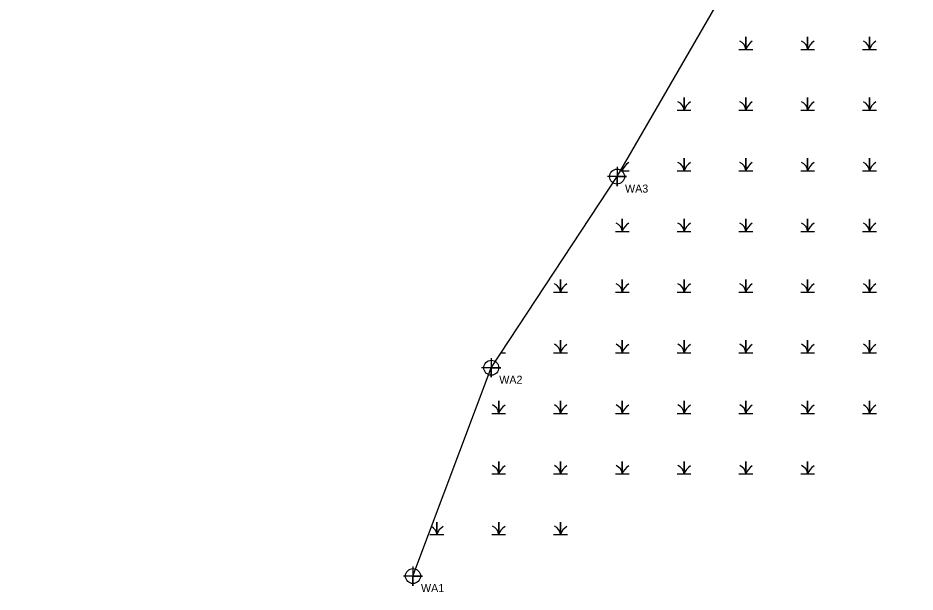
# Model space of a CAD drawing. Extents: x 2603618 to 2605510, y 618189 to 619022.
# Drawn here: x 2603635.1 to 2603915.3, y 618189.3 to 618368.6 of the extents above; entities that cross this region are included whole.
import ezdxf

# ---------------------------------------------------------------- set-up
doc = ezdxf.new("R2010")
doc.units = 0
for name, color, linetype in [('Exist Environmental Wetland Boundary', 7, 'Continuous'), ('Exist Environmental Wetland Boundary Cogo Comment', 7, 'Continuous'), ('Exist Environmental Wetland Boundary Cogo Point CELL', 7, 'Continuous')]:
    doc.layers.add(name, color=color, linetype=linetype)

msp = doc.modelspace()

# ---------------------------------------------------------------- linework, layer by layer
at = {"layer": 'Exist Environmental Wetland Boundary'}
for p, q in [((2603845.22, 618358.76), (2603845.33, 618358.76)), ((2603786.04, 618264.04), (2603787.43, 618264.04))]:
    msp.add_line(p, q, dxfattribs=at)
for points in [[(2603758.52, 618194.26), (2603782.96, 618259.35), (2603822.24, 618319.06), (2603863.83, 618390.93), (2603805.73, 618437.87), (2603772.56, 618472.6), (2603755.61, 618473.62), (2603701.62, 618448.45), (2603693.19, 618430.71), (2603667.96, 618396.56), (2603646.35, 618398.47), (2603635.91, 618407.07), (2603635.63, 618441.95), (2603635.14, 618475.26), (2603648.89, 618504.38), (2603719.39, 618530.95), (2603772.69, 618548.52), (2603823.7, 618526.04), (2603861.4, 618506.84), (2603897.92, 618497.01), (2603938.9, 618484.11)], [(2603860.33, 618358.76), (2603862.48, 618358.76), (2603862.48, 618362.71), (2603862.48, 618358.76), (2603864.63, 618358.76)], [(2603879.63, 618358.76), (2603881.78, 618358.76), (2603881.78, 618362.71), (2603881.78, 618358.76), (2603883.93, 618358.76)], [(2603898.93, 618358.76), (2603901.08, 618358.76), (2603901.08, 618362.71), (2603901.08, 618358.76), (2603903.23, 618358.76)], [(2603841.03, 618339.82), (2603843.18, 618339.82), (2603843.18, 618343.76), (2603843.18, 618339.82), (2603845.33, 618339.82)], [(2603860.33, 618339.82), (2603862.48, 618339.82), (2603862.48, 618343.76), (2603862.48, 618339.82), (2603864.63, 618339.82)], [(2603879.63, 618339.82), (2603881.78, 618339.82), (2603881.78, 618343.76), (2603881.78, 618339.82), (2603883.93, 618339.82)], [(2603898.93, 618339.82), (2603901.08, 618339.82), (2603901.08, 618343.76), (2603901.08, 618339.82), (2603903.23, 618339.82)], [(2603841.03, 618320.87), (2603843.18, 618320.87), (2603843.18, 618324.82), (2603843.18, 618320.87), (2603845.33, 618320.87)], [(2603860.33, 618320.87), (2603862.48, 618320.87), (2603862.48, 618324.82), (2603862.48, 618320.87), (2603864.63, 618320.87)], [(2603879.63, 618320.87), (2603881.78, 618320.87), (2603881.78, 618324.82), (2603881.78, 618320.87), (2603883.93, 618320.87)], [(2603898.93, 618320.87), (2603901.08, 618320.87), (2603901.08, 618324.82), (2603901.08, 618320.87), (2603903.23, 618320.87)], [(2603823.72, 618320.87), (2603823.88, 618320.87), (2603823.88, 618321.89)], [(2603823.88, 618321.89), (2603823.88, 618320.87), (2603826.03, 618320.87)], [(2603821.73, 618301.93), (2603823.88, 618301.93), (2603823.88, 618305.87), (2603823.88, 618301.93), (2603826.03, 618301.93)], [(2603841.03, 618301.93), (2603843.18, 618301.93), (2603843.18, 618305.87), (2603843.18, 618301.93), (2603845.33, 618301.93)], [(2603860.33, 618301.93), (2603862.48, 618301.93), (2603862.48, 618305.87), (2603862.48, 618301.93), (2603864.63, 618301.93)], [(2603879.63, 618301.93), (2603881.78, 618301.93), (2603881.78, 618305.87), (2603881.78, 618301.93), (2603883.93, 618301.93)], [(2603898.93, 618301.93), (2603901.08, 618301.93), (2603901.08, 618305.87), (2603901.08, 618301.93), (2603903.23, 618301.93)], [(2603802.43, 618282.98), (2603804.58, 618282.98), (2603804.58, 618286.93), (2603804.58, 618282.98), (2603806.73, 618282.98)], [(2603821.73, 618282.98), (2603823.88, 618282.98), (2603823.88, 618286.93), (2603823.88, 618282.98), (2603826.03, 618282.98)], [(2603841.03, 618282.98), (2603843.18, 618282.98), (2603843.18, 618286.93), (2603843.18, 618282.98), (2603845.33, 618282.98)], [(2603860.33, 618282.98), (2603862.48, 618282.98), (2603862.48, 618286.93), (2603862.48, 618282.98), (2603864.63, 618282.98)], [(2603879.63, 618282.98), (2603881.78, 618282.98), (2603881.78, 618286.93), (2603881.78, 618282.98), (2603883.93, 618282.98)], [(2603898.93, 618282.98), (2603901.08, 618282.98), (2603901.08, 618286.93), (2603901.08, 618282.98), (2603903.23, 618282.98)], [(2603802.43, 618264.04), (2603804.58, 618264.04), (2603804.58, 618267.98), (2603804.58, 618264.04), (2603806.73, 618264.04)], [(2603821.73, 618264.04), (2603823.88, 618264.04), (2603823.88, 618267.98), (2603823.88, 618264.04), (2603826.03, 618264.04)], [(2603841.03, 618264.04), (2603843.18, 618264.04), (2603843.18, 618267.98), (2603843.18, 618264.04), (2603845.33, 618264.04)], [(2603860.33, 618264.04), (2603862.48, 618264.04), (2603862.48, 618267.98), (2603862.48, 618264.04), (2603864.63, 618264.04)], [(2603879.63, 618264.04), (2603881.78, 618264.04), (2603881.78, 618267.98), (2603881.78, 618264.04), (2603883.93, 618264.04)], [(2603898.93, 618264.04), (2603901.08, 618264.04), (2603901.08, 618267.98), (2603901.08, 618264.04), (2603903.23, 618264.04)], [(2603783.12, 618245.09), (2603785.28, 618245.09), (2603785.28, 618249.04), (2603785.28, 618245.09), (2603787.43, 618245.09)], [(2603802.43, 618245.09), (2603804.58, 618245.09), (2603804.58, 618249.04), (2603804.58, 618245.09), (2603806.73, 618245.09)], [(2603821.73, 618245.09), (2603823.88, 618245.09), (2603823.88, 618249.04), (2603823.88, 618245.09), (2603826.03, 618245.09)], [(2603841.03, 618245.09), (2603843.18, 618245.09), (2603843.18, 618249.04), (2603843.18, 618245.09), (2603845.33, 618245.09)], [(2603860.33, 618245.09), (2603862.48, 618245.09), (2603862.48, 618249.04), (2603862.48, 618245.09), (2603864.63, 618245.09)], [(2603879.63, 618245.09), (2603881.78, 618245.09), (2603881.78, 618249.04), (2603881.78, 618245.09), (2603883.93, 618245.09)], [(2603898.93, 618245.09), (2603901.08, 618245.09), (2603901.08, 618249.04), (2603901.08, 618245.09), (2603903.23, 618245.09)], [(2603783.12, 618226.15), (2603785.28, 618226.15), (2603785.28, 618230.09), (2603785.28, 618226.15), (2603787.43, 618226.15)], [(2603802.43, 618226.15), (2603804.58, 618226.15), (2603804.58, 618230.09), (2603804.58, 618226.15), (2603806.73, 618226.15)], [(2603821.73, 618226.15), (2603823.88, 618226.15), (2603823.88, 618230.09), (2603823.88, 618226.15), (2603826.03, 618226.15)], [(2603841.03, 618226.15), (2603843.18, 618226.15), (2603843.18, 618230.09), (2603843.18, 618226.15), (2603845.33, 618226.15)], [(2603860.33, 618226.15), (2603862.48, 618226.15), (2603862.48, 618230.09), (2603862.48, 618226.15), (2603864.63, 618226.15)], [(2603879.63, 618226.15), (2603881.78, 618226.15), (2603881.78, 618230.09), (2603881.78, 618226.15), (2603883.93, 618226.15)], [(2603763.82, 618207.2), (2603765.97, 618207.2), (2603765.97, 618211.15), (2603765.97, 618207.2), (2603768.12, 618207.2)], [(2603783.12, 618207.2), (2603785.28, 618207.2), (2603785.28, 618211.15), (2603785.28, 618207.2), (2603787.43, 618207.2)], [(2603802.43, 618207.2), (2603804.58, 618207.2), (2603804.58, 618211.15), (2603804.58, 618207.2), (2603806.73, 618207.2)]]:
    msp.add_lwpolyline(points, dxfattribs=at)
for centre, radius, start, end in [((2603859.41, 618358.54), 3.07, 4.1403, 67.535), ((2603867.04, 618357.25), 4.81, 122.1274, 161.6222), ((2603878.71, 618358.54), 3.07, 4.1403, 67.535), ((2603886.34, 618357.25), 4.81, 122.1274, 161.6222), ((2603898.01, 618358.54), 3.07, 4.1403, 67.535), ((2603905.64, 618357.25), 4.81, 122.1274, 161.6222), ((2603840.11, 618339.6), 3.07, 4.1403, 67.535), ((2603847.74, 618338.3), 4.81, 122.1274, 161.6222), ((2603859.41, 618339.6), 3.07, 4.1403, 67.535), ((2603867.04, 618338.3), 4.81, 122.1274, 161.6222), ((2603878.71, 618339.6), 3.07, 4.1403, 67.535), ((2603886.34, 618338.3), 4.81, 122.1274, 161.6222), ((2603898.01, 618339.6), 3.07, 4.1403, 67.535), ((2603905.64, 618338.3), 4.81, 122.1274, 161.6222), ((2603828.44, 618319.36), 4.81, 122.1274, 161.6222), ((2603840.11, 618320.65), 3.07, 4.1403, 67.535), ((2603847.74, 618319.36), 4.81, 122.1274, 161.6222), ((2603859.41, 618320.65), 3.07, 4.1403, 67.535), ((2603867.04, 618319.36), 4.81, 122.1274, 161.6222), ((2603878.71, 618320.65), 3.07, 4.1403, 67.535), ((2603886.34, 618319.36), 4.81, 122.1274, 161.6222), ((2603898.01, 618320.65), 3.07, 4.1403, 67.535), ((2603905.64, 618319.36), 4.81, 122.1274, 161.6222), ((2603820.81, 618320.65), 3.07, 4.1403, 18.5214), ((2603820.81, 618301.71), 3.07, 4.1403, 67.535), ((2603828.44, 618300.41), 4.81, 122.1274, 161.6222), ((2603840.11, 618301.71), 3.07, 4.1403, 67.535), ((2603847.74, 618300.41), 4.81, 122.1274, 161.6222), ((2603859.41, 618301.71), 3.07, 4.1403, 67.535), ((2603867.04, 618300.41), 4.81, 122.1274, 161.6222), ((2603878.71, 618301.71), 3.07, 4.1403, 67.535), ((2603886.34, 618300.41), 4.81, 122.1274, 161.6222), ((2603898.01, 618301.71), 3.07, 4.1403, 67.535), ((2603905.64, 618300.41), 4.81, 122.1274, 161.6222), ((2603801.51, 618282.76), 3.07, 4.1403, 67.535), ((2603809.14, 618281.47), 4.81, 122.1274, 161.6222), ((2603820.81, 618282.76), 3.07, 4.1403, 67.535), ((2603828.44, 618281.47), 4.81, 122.1274, 161.6222), ((2603840.11, 618282.76), 3.07, 4.1403, 67.535), ((2603847.74, 618281.47), 4.81, 122.1274, 161.6222), ((2603859.41, 618282.76), 3.07, 4.1403, 67.535), ((2603867.04, 618281.47), 4.81, 122.1274, 161.6222), ((2603878.71, 618282.76), 3.07, 4.1403, 67.535), ((2603886.34, 618281.47), 4.81, 122.1274, 161.6222), ((2603898.01, 618282.76), 3.07, 4.1403, 67.535), ((2603905.64, 618281.47), 4.81, 122.1274, 161.6222), ((2603801.51, 618263.82), 3.07, 4.1403, 67.535), ((2603809.14, 618262.52), 4.81, 122.1274, 161.6222), ((2603820.81, 618263.82), 3.07, 4.1403, 67.535), ((2603828.44, 618262.52), 4.81, 122.1274, 161.6222), ((2603840.11, 618263.82), 3.07, 4.1403, 67.535), ((2603847.74, 618262.52), 4.81, 122.1274, 161.6222), ((2603859.41, 618263.82), 3.07, 4.1403, 67.535), ((2603867.04, 618262.52), 4.81, 122.1274, 161.6222), ((2603878.71, 618263.82), 3.07, 4.1403, 67.535), ((2603886.34, 618262.52), 4.81, 122.1274, 161.6222), ((2603898.01, 618263.82), 3.07, 4.1403, 67.535), ((2603905.64, 618262.52), 4.81, 122.1274, 161.6222), ((2603782.21, 618244.87), 3.07, 4.1403, 67.535), ((2603789.84, 618243.58), 4.81, 122.1274, 161.6222), ((2603801.51, 618244.87), 3.07, 4.1403, 67.535), ((2603809.14, 618243.58), 4.81, 122.1274, 161.6222), ((2603820.81, 618244.87), 3.07, 4.1403, 67.535), ((2603828.44, 618243.58), 4.81, 122.1274, 161.6222), ((2603840.11, 618244.87), 3.07, 4.1403, 67.535), ((2603847.74, 618243.58), 4.81, 122.1274, 161.6222), ((2603859.41, 618244.87), 3.07, 4.1403, 67.535), ((2603867.04, 618243.58), 4.81, 122.1274, 161.6222), ((2603878.71, 618244.87), 3.07, 4.1403, 67.535), ((2603886.34, 618243.58), 4.81, 122.1274, 161.6222), ((2603898.01, 618244.87), 3.07, 4.1403, 67.535), ((2603905.64, 618243.58), 4.81, 122.1274, 161.6222), ((2603782.21, 618225.93), 3.07, 4.1403, 67.535), ((2603789.84, 618224.63), 4.81, 122.1274, 161.6222), ((2603801.51, 618225.93), 3.07, 4.1403, 67.535), ((2603809.14, 618224.63), 4.81, 122.1274, 161.6222), ((2603820.81, 618225.93), 3.07, 4.1403, 67.535), ((2603828.44, 618224.63), 4.81, 122.1274, 161.6222), ((2603840.11, 618225.93), 3.07, 4.1403, 67.535), ((2603847.74, 618224.63), 4.81, 122.1274, 161.6222), ((2603859.41, 618225.93), 3.07, 4.1403, 67.535), ((2603867.04, 618224.63), 4.81, 122.1274, 161.6222), ((2603878.71, 618225.93), 3.07, 4.1403, 67.535), ((2603886.34, 618224.63), 4.81, 122.1274, 161.6222), ((2603762.91, 618206.98), 3.07, 4.1403, 62.6599), ((2603770.53, 618205.69), 4.81, 122.1274, 161.6222), ((2603782.21, 618206.98), 3.07, 4.1403, 67.535), ((2603789.84, 618205.69), 4.81, 122.1274, 161.6222), ((2603801.51, 618206.98), 3.07, 4.1403, 67.535), ((2603809.14, 618205.69), 4.81, 122.1274, 161.6222)]:
    msp.add_arc(centre, radius, start, end, dxfattribs=at)
at = {"layer": 'Exist Environmental Wetland Boundary Cogo Point CELL'}
for points in [[(2603822.24, 618322.06), (2603822.24, 618316.06), (2603822.24, 618319.06), (2603825.24, 618319.06), (2603819.24, 618319.06)], [(2603782.96, 618262.35), (2603782.96, 618256.35), (2603782.96, 618259.35), (2603785.96, 618259.35), (2603779.96, 618259.35)], [(2603758.52, 618197.26), (2603758.52, 618191.26), (2603758.52, 618194.26), (2603761.52, 618194.26), (2603755.52, 618194.26)]]:
    msp.add_lwpolyline(points, dxfattribs=at)
for centre in [(2603822.24, 618319.06), (2603782.96, 618259.35), (2603758.52, 618194.26)]:
    msp.add_circle(centre, 2.34, dxfattribs=at)

# ---------------------------------------------------------------- texts
at = {"layer": 'Exist Environmental Wetland Boundary Cogo Comment'}
for s, p in [('WA3', (2603824.74, 618314.06)), ('WA2', (2603785.46, 618254.35)), ('WA1', (2603761.02, 618189.26))]:
    msp.add_text(s, height=2.5, dxfattribs=at).set_placement(p)

doc.saveas('drawing.dxf')
